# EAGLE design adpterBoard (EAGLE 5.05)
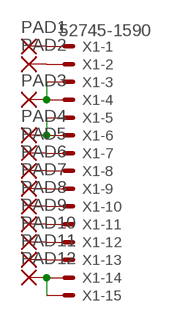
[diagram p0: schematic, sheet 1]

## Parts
PAD1  2,15/1,0  [2,15/1,0]
PAD2  2,15/1,0  [2,15/1,0]
PAD3  2,15/1,0  [2,15/1,0]
PAD4  2,15/1,0  [2,15/1,0]
PAD5  2,15/1,0  [2,15/1,0]
PAD6  2,15/1,0  [2,15/1,0]
PAD7  2,15/1,0  [2,15/1,0]
PAD8  2,15/1,0  [2,15/1,0]
PAD9  2,15/1,0  [2,15/1,0]
PAD10  2,15/1,0  [2,15/1,0]
PAD11  2,15/1,0  [2,15/1,0]
PAD12  2,15/1,0  [2,15/1,0]
X1  52745-1590  [52745-1590]

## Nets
N$1: PAD1.1(P) X1.1
N$2: PAD2.1(P) X1.2
N$3: PAD3.1(P) X1.3 X1.4
N$4: PAD4.1(P) X1.5 X1.6
N$5: PAD12.1(P) X1.14 X1.15
N$6: PAD5.1(P) X1.7
N$7: PAD6.1(P) X1.8
N$8: PAD7.1(P) X1.9
N$9: PAD8.1(P) X1.10
N$10: PAD9.1(P) X1.11
N$11: PAD10.1(P) X1.12
N$12: PAD11.1(P) X1.13

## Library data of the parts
PAD1-PAD12 = wirepad:2,15/1,0: THROUGH-HOLE PAD
X1 = con-molex:52745-1590: FFC/FPC-to-Board 0.50mm (.020") SMT Top Contact Right Angle, ZIF, Style Receptacle 52745 / 52435 Source: http://www.molex.com/product/ffc/52745.html

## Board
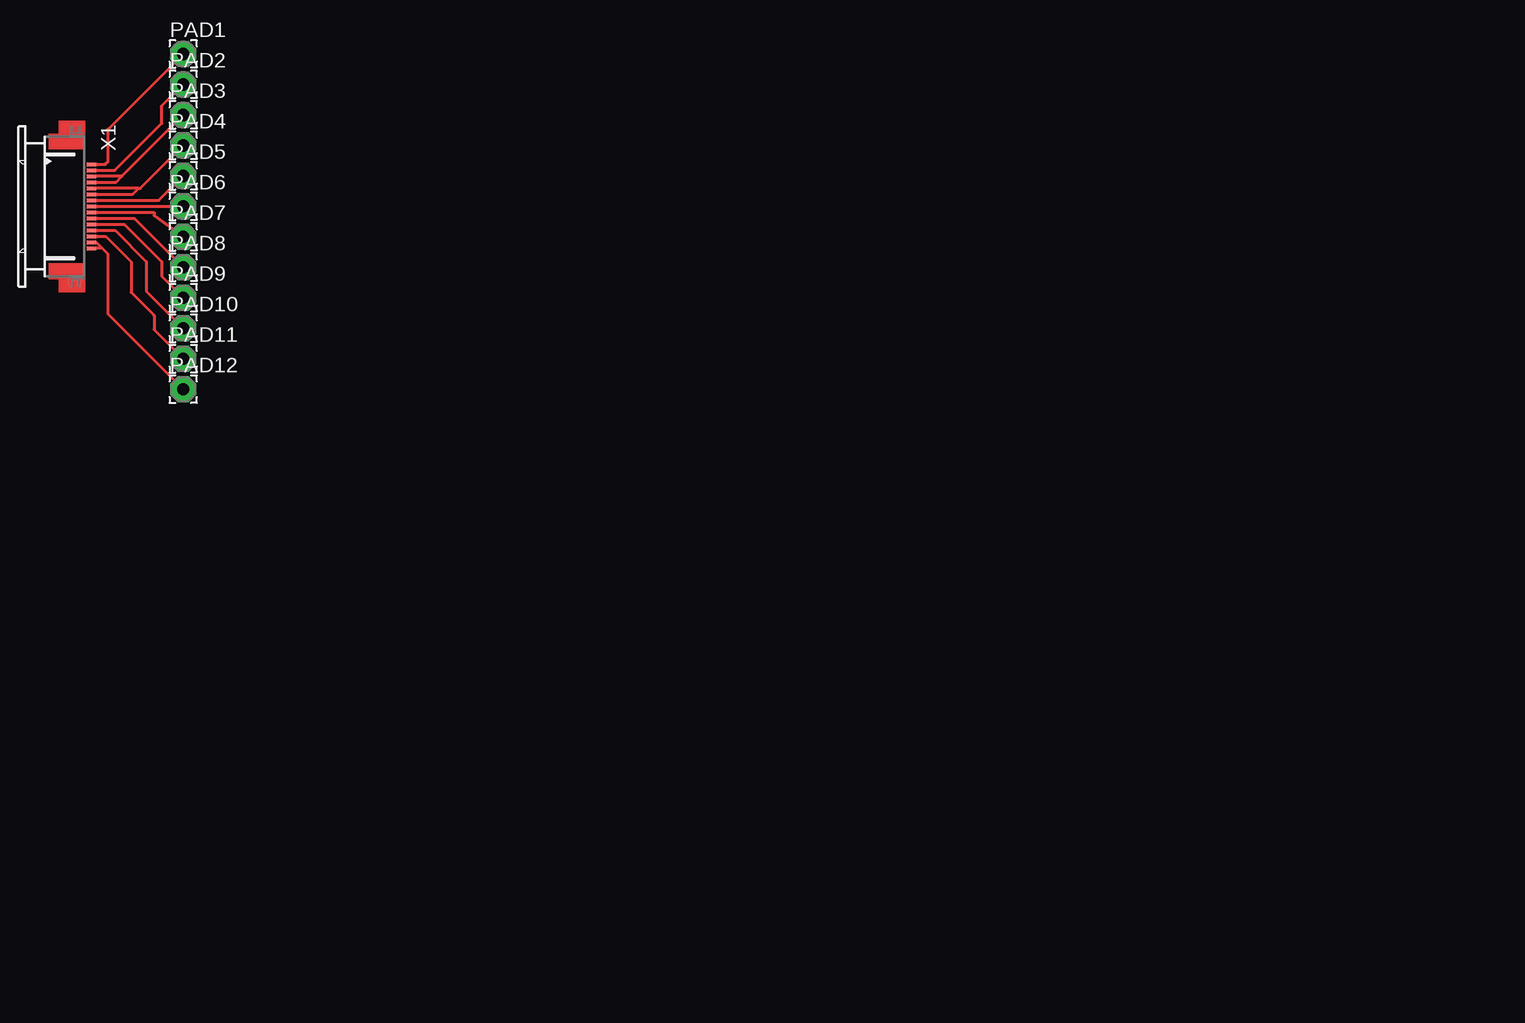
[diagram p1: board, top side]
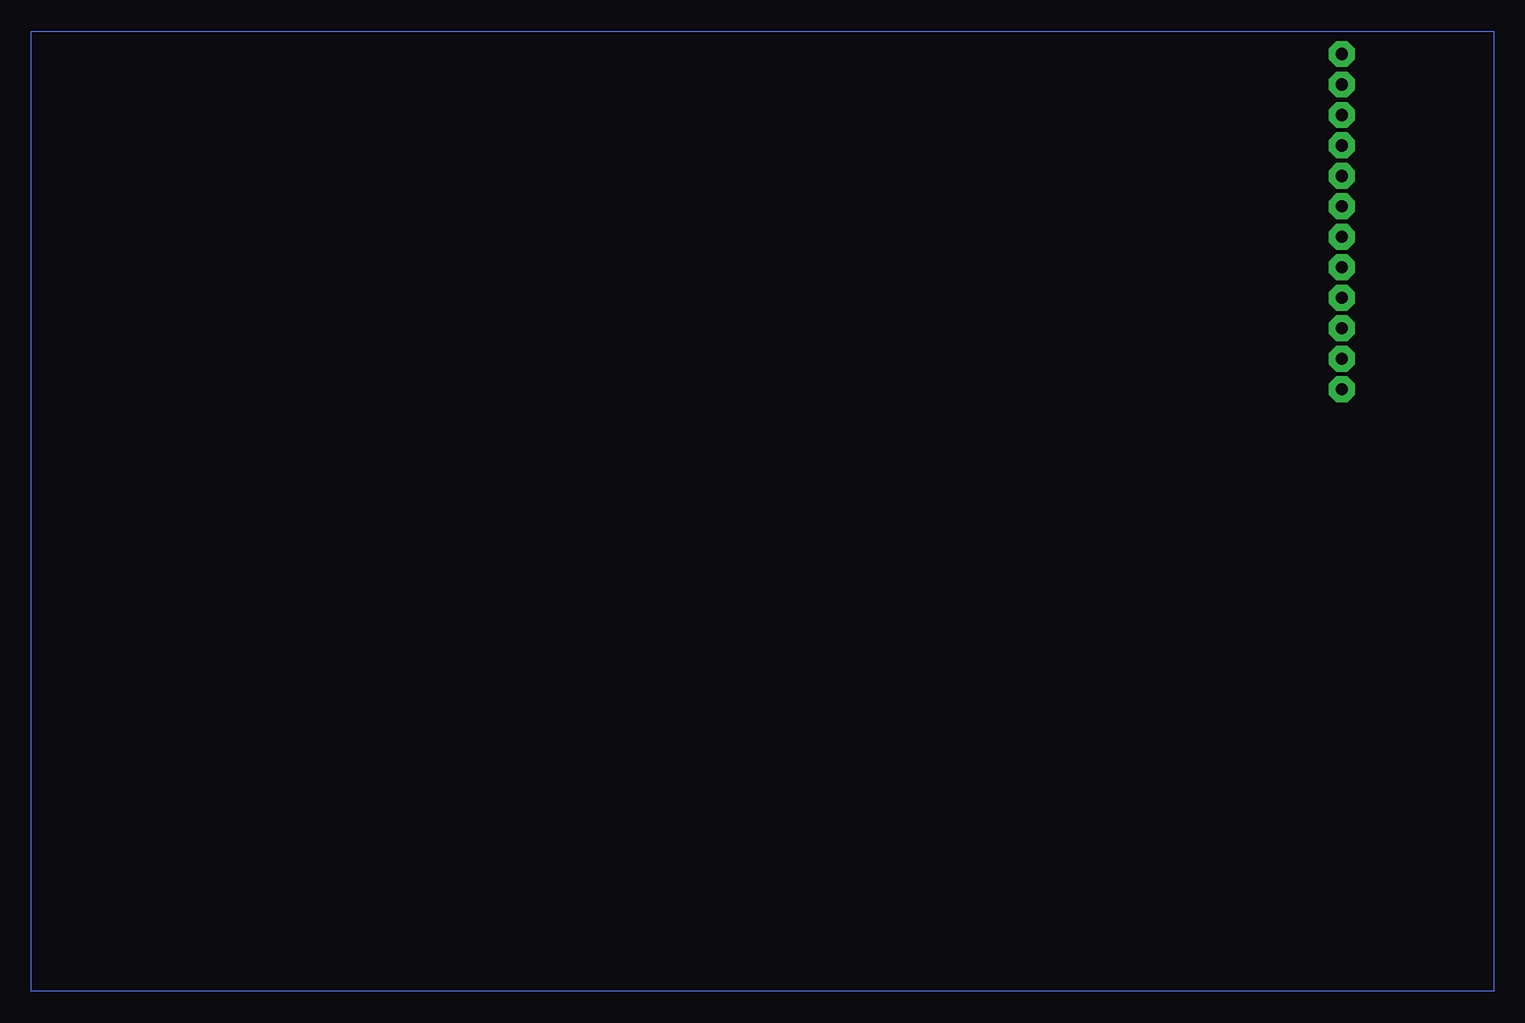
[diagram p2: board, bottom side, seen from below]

No outline drawn. Coordinates in mm, seen from the top.
Copper layers (1*16): Top 0.035mm / dielectric 1.5mm / Bottom 0.035mm
Design rules "default": minimum track width 10mil, minimum drill 24mil, track to track 8mil, track to pad 8mil, pad to pad 8mil, via to via 8mil, smd to smd 8mil, copper to edge 40mil, drill to drill 8mil, minimum pad ring 10mil, minimum via ring 8mil, stop-mask expansion 4mil, vias tented up to drill 0mil, thermal gap 10mil

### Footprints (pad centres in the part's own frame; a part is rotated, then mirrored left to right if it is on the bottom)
2,15/1,0 = drill 1.016 pad 2.159 octagon: 1 0,0
52745-1590 = smd 0.3 x 0.8: 1 -3.5,2.5; 2 -3,2.5; 3 -2.5,2.5; 4 -2,2.5; 5 -1.5,2.5; 6 -1,2.5; 7 -0.5,2.5; 8 0,2.5; 9 0.5,2.5; 10 1,2.5; 11 1.5,2.5; 12 2,2.5; 13 2.5,2.5; 14 3,2.5; 15 3.5,2.5

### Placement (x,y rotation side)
PAD1  12.67,78.11 0 top
PAD2  12.67,75.57 0 top
PAD3  12.67,73.03 0 top
PAD4  12.67,70.49 0 top
PAD5  12.67,67.95 0 top
PAD6  12.67,65.41 0 top
PAD7  12.67,62.87 0 top
PAD8  12.67,60.33 0 top
PAD9  12.67,57.79 0 top
PAD10  12.67,55.25 0 top
PAD11  12.67,52.71 0 top
PAD12  12.67,50.17 0 top
X1  2.51,65.41 270 top

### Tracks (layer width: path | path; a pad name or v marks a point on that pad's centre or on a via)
N$1
  Top 0.254: X1.1 6.19,68.91 6.4,69.12 6.4,71.84 PAD1.1
N$2
  Top 0.254: X1.2 6.97,68.41 10.88,72.32 10.88,73.78 PAD2.1
N$3
  Top 0.254: X1.4 5.06,67.44 7.08,67.44 7.55,67.91 | 5.06,67.84 X1.3 7.55,67.91 | 7.55,67.91 PAD3.1
N$4
  Top 0.254: 8.96,66.91 X1.5 | 8.96,66.91 9.09,66.91 PAD4.1 | X1.6 8.46,66.41 8.96,66.91
N$5
  Top 0.254: X1.15 5.06,61.94 5.9,61.94 | X1.14 5.06,62.34 5.5,62.34 5.9,61.94 | 5.9,61.94 6.4,61.44 6.4,56.44 PAD12.1
N$6
  Top 0.254: X1.7 10.63,65.91 PAD5.1
N$7
  Top 0.254: X1.8 PAD6.1
N$8
  Top 0.254: X1.9 10.24,64.91 10.24,64.64 PAD7.1
N$9
  Top 0.254: X1.10 8.59,64.41 PAD8.1
N$10
  Top 0.254: X1.11 7.77,63.91 10.88,60.8 10.88,59.58 PAD9.1
N$11
  Top 0.254: X1.12 6.99,63.41 9.6,60.8 9.6,58.32 PAD10.1
N$12
  Top 0.254: X1.13 6.21,62.91 8.32,60.8 8.32,58.24 10.24,56.32 10.24,55.14 PAD11.1
(copper drawn outside any net)
  shapes: Bottom area x1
